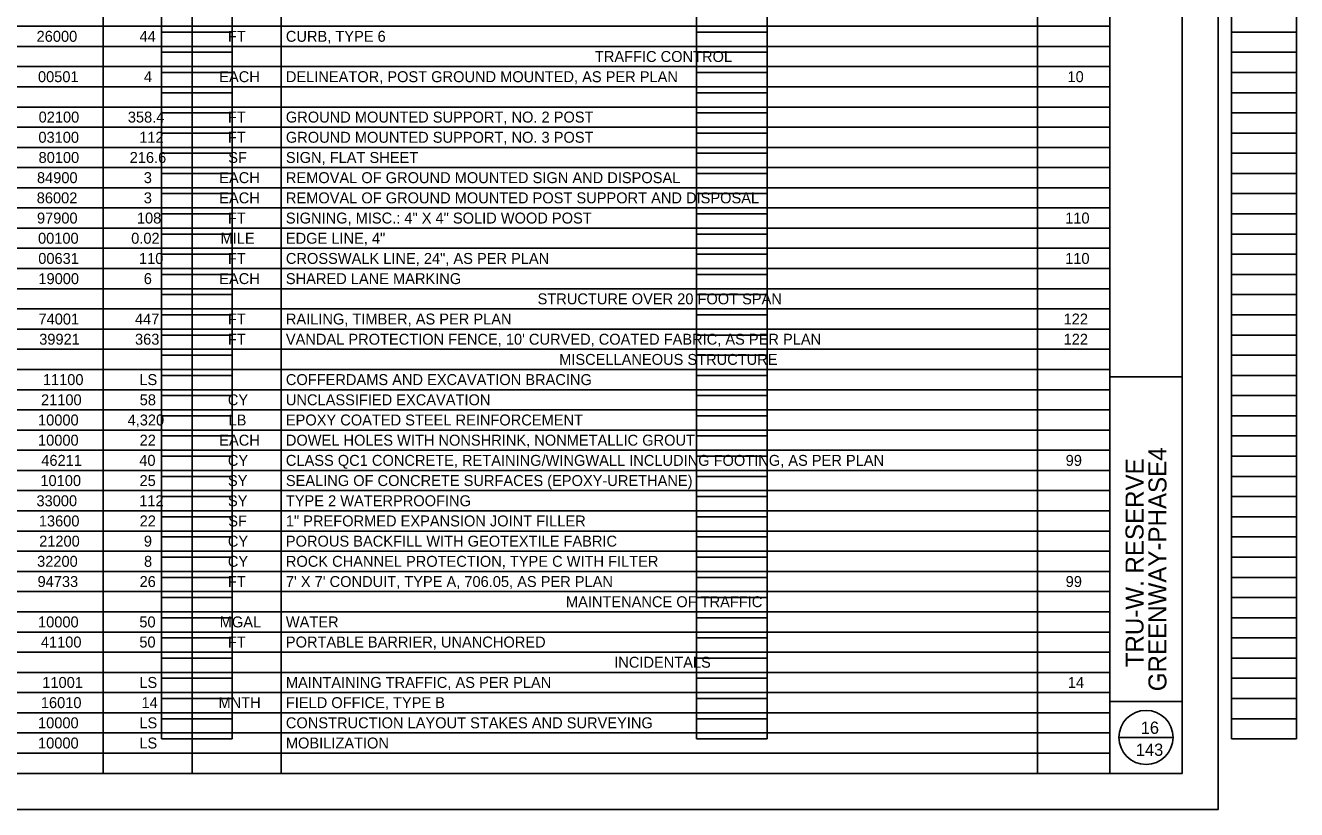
# Model space of a CAD drawing. Extents: x -16 to 102, y -13 to 9.
# Drawn here: x 44.51 to 62.14, y -12.91 to -2.03 of the extents above; entities that cross this region are included whole.
import ezdxf

# ---------------------------------------------------------------- set-up
doc = ezdxf.new("R2010")
doc.units = 0
for name, color, linetype in [('PV_P_EOP', 7, 'Continuous'), ('SH_Border', 7, 'Continuous'), ('SH_Cut_Line', 7, 'Continuous'), ('SH_Data', 7, 'Continuous'), ('TX_P_1', 7, 'Continuous')]:
    doc.layers.add(name, color=color, linetype=linetype)

msp = doc.modelspace()

# ---------------------------------------------------------------- linework, layer by layer
at = {"layer": 'SH_Border'}
for p, q in [((59.554, -12.407), (59.554, 8.593)), ((59.554, -6.907), (60.554, -6.907)), ((59.554, -11.407), (60.554, -11.407))]:
    msp.add_line(p, q, dxfattribs=at)
msp.add_lwpolyline([(29.054, 8.593), (60.554, 8.593), (60.554, -12.407), (29.054, -12.407)], close=True, dxfattribs=at)
at = {"layer": 'SH_Cut_Line'}
msp.add_lwpolyline([(27.054, -12.907), (61.054, -12.907), (61.054, 9.093), (27.054, 9.093)], close=True, dxfattribs=at)
at = {"layer": 'SH_Data'}
for p, q in [((46.402, -11.927), (46.402, 8.233)), ((47.382, -11.927), (47.382, 8.233)), ((53.822, -11.927), (53.822, 8.233)), ((54.802, -11.927), (54.802, 8.233)), ((61.242, -11.927), (61.242, 8.233)), ((62.142, -11.927), (62.142, 8.233)), ((46.402, -2.127), (47.382, -2.127)), ((53.822, -2.127), (54.802, -2.127)), ((61.242, -2.127), (62.142, -2.127)), ((46.402, -2.407), (47.382, -2.407)), ((53.822, -2.407), (54.802, -2.407)), ((61.242, -2.407), (62.142, -2.407)), ((46.402, -2.687), (47.382, -2.687)), ((53.822, -2.687), (54.802, -2.687)), ((61.242, -2.687), (62.142, -2.687)), ((46.402, -2.967), (47.382, -2.967)), ((53.822, -2.967), (54.802, -2.967)), ((61.242, -2.967), (62.142, -2.967)), ((46.402, -3.247), (47.382, -3.247)), ((53.822, -3.247), (54.802, -3.247)), ((61.242, -3.247), (62.142, -3.247)), ((46.402, -3.527), (47.382, -3.527)), ((53.822, -3.527), (54.802, -3.527)), ((61.242, -3.527), (62.142, -3.527)), ((46.402, -3.807), (47.382, -3.807)), ((53.822, -3.807), (54.802, -3.807)), ((61.242, -3.807), (62.142, -3.807)), ((46.402, -4.087), (47.382, -4.087)), ((53.822, -4.087), (54.802, -4.087)), ((61.242, -4.087), (62.142, -4.087)), ((46.402, -4.367), (47.382, -4.367)), ((53.822, -4.367), (54.802, -4.367)), ((61.242, -4.367), (62.142, -4.367)), ((46.402, -4.647), (47.382, -4.647)), ((53.822, -4.647), (54.802, -4.647)), ((61.242, -4.647), (62.142, -4.647)), ((46.402, -4.927), (47.382, -4.927)), ((53.822, -4.927), (54.802, -4.927)), ((61.242, -4.927), (62.142, -4.927)), ((46.402, -5.207), (47.382, -5.207)), ((53.822, -5.207), (54.802, -5.207)), ((61.242, -5.207), (62.142, -5.207)), ((46.402, -5.487), (47.382, -5.487)), ((53.822, -5.487), (54.802, -5.487)), ((61.242, -5.487), (62.142, -5.487)), ((46.402, -5.767), (47.382, -5.767)), ((53.822, -5.767), (54.802, -5.767)), ((61.242, -5.767), (62.142, -5.767)), ((46.402, -6.047), (47.382, -6.047)), ((53.822, -6.047), (54.802, -6.047)), ((61.242, -6.047), (62.142, -6.047)), ((46.402, -6.327), (47.382, -6.327)), ((53.822, -6.327), (54.802, -6.327)), ((61.242, -6.327), (62.142, -6.327)), ((46.402, -6.607), (47.382, -6.607)), ((53.822, -6.607), (54.802, -6.607)), ((61.242, -6.607), (62.142, -6.607)), ((46.402, -6.887), (47.382, -6.887)), ((53.822, -6.887), (54.802, -6.887)), ((61.242, -6.887), (62.142, -6.887)), ((46.402, -7.167), (47.382, -7.167)), ((53.822, -7.167), (54.802, -7.167)), ((61.242, -7.167), (62.142, -7.167)), ((46.402, -7.447), (47.382, -7.447)), ((53.822, -7.447), (54.802, -7.447)), ((61.242, -7.447), (62.142, -7.447)), ((46.402, -7.727), (47.382, -7.727)), ((53.822, -7.727), (54.802, -7.727)), ((61.242, -7.727), (62.142, -7.727)), ((46.402, -8.007), (47.382, -8.007)), ((53.822, -8.007), (54.802, -8.007)), ((61.242, -8.007), (62.142, -8.007)), ((46.402, -8.287), (47.382, -8.287)), ((53.822, -8.287), (54.802, -8.287)), ((61.242, -8.287), (62.142, -8.287)), ((46.402, -8.567), (47.382, -8.567)), ((53.822, -8.567), (54.802, -8.567)), ((61.242, -8.567), (62.142, -8.567)), ((46.402, -8.847), (47.382, -8.847)), ((53.822, -8.847), (54.802, -8.847)), ((61.242, -8.847), (62.142, -8.847)), ((46.402, -9.127), (47.382, -9.127)), ((53.822, -9.127), (54.802, -9.127)), ((61.242, -9.127), (62.142, -9.127)), ((46.402, -9.407), (47.382, -9.407)), ((53.822, -9.407), (54.802, -9.407)), ((61.242, -9.407), (62.142, -9.407)), ((46.402, -9.687), (47.382, -9.687)), ((53.822, -9.687), (54.802, -9.687)), ((61.242, -9.687), (62.142, -9.687)), ((46.402, -9.967), (47.382, -9.967)), ((53.822, -9.967), (54.802, -9.967)), ((61.242, -9.967), (62.142, -9.967)), ((46.402, -10.247), (47.382, -10.247)), ((53.822, -10.247), (54.802, -10.247)), ((61.242, -10.247), (62.142, -10.247)), ((46.402, -10.527), (47.382, -10.527)), ((53.822, -10.527), (54.802, -10.527)), ((61.242, -10.527), (62.142, -10.527)), ((46.402, -10.807), (47.382, -10.807)), ((53.822, -10.807), (54.802, -10.807)), ((61.242, -10.807), (62.142, -10.807)), ((46.402, -11.087), (47.382, -11.087)), ((53.822, -11.087), (54.802, -11.087)), ((61.242, -11.087), (62.142, -11.087)), ((46.402, -11.367), (47.382, -11.367)), ((53.822, -11.367), (54.802, -11.367)), ((61.242, -11.367), (62.142, -11.367)), ((46.402, -11.647), (47.382, -11.647)), ((53.822, -11.647), (54.802, -11.647)), ((61.242, -11.647), (62.142, -11.647)), ((46.402, -11.927), (47.382, -11.927)), ((53.822, -11.927), (54.802, -11.927)), ((59.679, -11.907), (60.429, -11.907)), ((61.242, -11.927), (62.142, -11.927))]:
    msp.add_line(p, q, dxfattribs=at)
msp.add_circle((60.054, -11.907), 0.375, dxfattribs=at)
at = {"layer": 'TX_P_1'}
for p, q in [((45.589, 8.593), (45.589, -12.405)), ((46.824, 8.593), (46.824, -12.405)), ((48.059, 8.593), (48.059, -12.405)), ((58.549, 8.593), (58.549, -12.405)), ((59.554, 8.593), (59.554, -12.405)), ((29.054, -2.046), (59.554, -2.046)), ((29.054, -2.326), (59.554, -2.326)), ((29.054, -2.606), (59.554, -2.606)), ((29.054, -2.886), (59.554, -2.886)), ((29.054, -3.166), (59.554, -3.166)), ((29.054, -3.446), (59.554, -3.446)), ((29.054, -3.726), (59.554, -3.726)), ((29.054, -4.005), (59.554, -4.005)), ((29.054, -4.285), (59.554, -4.285)), ((29.054, -4.565), (59.554, -4.565)), ((29.054, -4.845), (59.554, -4.845)), ((29.054, -5.125), (59.554, -5.125)), ((29.054, -5.405), (59.554, -5.405)), ((29.054, -5.685), (59.554, -5.685)), ((29.054, -5.965), (59.554, -5.965)), ((29.054, -6.245), (59.554, -6.245)), ((29.054, -6.525), (59.554, -6.525)), ((29.054, -6.805), (59.554, -6.805)), ((29.054, -7.085), (59.554, -7.085)), ((29.054, -7.365), (59.554, -7.365)), ((29.054, -7.645), (59.554, -7.645)), ((29.054, -7.925), (59.554, -7.925)), ((29.054, -8.205), (59.554, -8.205)), ((29.054, -8.485), (59.554, -8.485)), ((29.054, -8.765), (59.554, -8.765)), ((29.054, -9.045), (59.554, -9.045)), ((29.054, -9.325), (59.554, -9.325)), ((29.054, -9.605), (59.554, -9.605)), ((29.054, -9.885), (59.554, -9.885)), ((29.054, -10.165), (59.554, -10.165)), ((29.054, -10.445), (59.554, -10.445)), ((29.054, -10.725), (59.554, -10.725)), ((29.054, -11.005), (59.554, -11.005)), ((29.054, -11.285), (59.554, -11.285)), ((29.054, -11.565), (59.554, -11.565)), ((29.054, -11.845), (59.554, -11.845)), ((29.054, -12.125), (59.554, -12.125)), ((29.054, -12.405), (59.554, -12.405))]:
    msp.add_line(p, q, dxfattribs=at)

# ---------------------------------------------------------------- texts
at = {"layer": 'PV_P_EOP'}
for s, p in [('TRAFFIC CONTROL', (52.411, -2.541)), ('STRUCTURE OVER 20 FOOT SPAN ', (51.616, -5.901)), ('MISCELLANEOUS STRUCTURE', (51.915, -6.741)), ('MAINTENANCE OF TRAFFIC', (52.009, -10.101)), ('INCIDENTALS', (52.679, -10.94))]:
    msp.add_text(s, height=0.15151, dxfattribs=at).set_placement(p)
at = {"layer": 'SH_Data'}
for s, p in [('GREENWAY-PHASE4', (60.338, -11.266)), ('TRU-W. RESERVE', (60.02, -10.934))]:
    msp.add_text(s, height=0.25, rotation=90, dxfattribs=at).set_placement(p)
for s, p in [('16', (59.981, -11.857)), ('143', (59.914, -12.162))]:
    msp.add_text(s, height=0.17, dxfattribs=at).set_placement(p)
at = {"layer": 'TX_P_1'}
for s, height, p in [('26000', 0.1515, (44.668, -2.261)), ('44', 0.1515, (46.096, -2.261)), ('FT', 0.1515, (47.322, -2.261)), ('CURB, TYPE 6', 0.15151, (48.125, -2.261)), ('00501', 0.1515, (44.687, -2.821)), ('4', 0.152, (46.156, -2.821)), ('EACH', 0.1515, (47.201, -2.821)), ('DELINEATOR, POST GROUND MOUNTED, AS PER PLAN', 0.15151, (48.125, -2.821)), ('10', 0.1515, (58.965, -2.821)), ('02100', 0.1515, (44.696, -3.381)), ('358.4', 0.1515, (45.933, -3.381)), ('FT', 0.1515, (47.322, -3.381)), ('GROUND MOUNTED SUPPORT, NO. 2 POST', 0.15151, (48.125, -3.381)), ('03100', 0.1515, (44.693, -3.661)), ('112', 0.1515, (46.091, -3.661)), ('FT', 0.1515, (47.322, -3.661)), ('GROUND MOUNTED SUPPORT, NO. 3 POST', 0.15151, (48.125, -3.661)), ('80100', 0.1515, (44.695, -3.941)), ('216.6', 0.1515, (45.959, -3.941)), ('SF', 0.1515, (47.326, -3.941)), ('SIGN, FLAT SHEET', 0.15151, (48.125, -3.941)), ('84900', 0.1515, (44.673, -4.221)), ('3', 0.152, (46.154, -4.221)), ('EACH', 0.1515, (47.201, -4.221)), ('REMOVAL OF GROUND MOUNTED SIGN AND DISPOSAL', 0.15151, (48.125, -4.221)), ('86002', 0.1515, (44.67, -4.501)), ('3', 0.152, (46.154, -4.501)), ('EACH', 0.1515, (47.201, -4.501)), ('REMOVAL OF GROUND MOUNTED POST SUPPORT AND DISPOSAL', 0.15151, (48.125, -4.501)), ('97900', 0.1515, (44.673, -4.781)), ('108', 0.1515, (46.059, -4.781)), ('FT', 0.1515, (47.322, -4.781)), ('SIGNING, MISC.: 4" X 4" SOLID WOOD POST', 0.15151, (48.125, -4.781)), ('110', 0.1515, (58.933, -4.781)), ('00100', 0.1515, (44.688, -5.061)), ('0.02', 0.1515, (45.98, -5.061)), ('MILE', 0.1515, (47.22, -5.061)), ('EDGE LINE, 4"', 0.15151, (48.125, -5.061)), ('00631', 0.1515, (44.691, -5.341)), ('110', 0.1515, (46.088, -5.341)), ('FT', 0.1515, (47.322, -5.341)), ('CROSSWALK LINE, 24", AS PER PLAN', 0.15151, (48.125, -5.341)), ('110', 0.1515, (58.933, -5.341)), ('19000', 0.1515, (44.693, -5.621)), ('6', 0.152, (46.154, -5.621)), ('EACH', 0.1515, (47.201, -5.621)), ('SHARED LANE MARKING', 0.15151, (48.125, -5.621)), ('74001', 0.1515, (44.694, -6.181)), ('447', 0.1515, (46.032, -6.181)), ('FT', 0.1515, (47.322, -6.181)), ('RAILING, TIMBER, AS PER PLAN', 0.15151, (48.125, -6.181)), ('122', 0.1515, (58.911, -6.181)), ('39921', 0.1515, (44.704, -6.461)), ('363', 0.1515, (46.033, -6.461)), ('FT', 0.1515, (47.322, -6.461)), ("VANDAL PROTECTION FENCE, 10' CURVED, COATED FABRIC, AS PER PLAN", 0.15151, (48.125, -6.461)), ('122', 0.1515, (58.911, -6.461)), ('11100', 0.1515, (44.755, -7.021)), ('LS', 0.1515, (46.093, -7.021)), ('COFFERDAMS AND EXCAVATION BRACING', 0.15151, (48.125, -7.021)), ('21100', 0.1515, (44.729, -7.301)), ('58', 0.1515, (46.098, -7.301)), ('CY', 0.1515, (47.32, -7.301)), ('UNCLASSIFIED EXCAVATION', 0.15151, (48.125, -7.301)), ('10000', 0.1515, (44.688, -7.581)), ('4,320', 0.1515, (45.93, -7.581)), ('LB', 0.1515, (47.33, -7.581)), ('EPOXY COATED STEEL REINFORCEMENT', 0.15151, (48.125, -7.581)), ('10000', 0.1515, (44.688, -7.861)), ('22', 0.1515, (46.097, -7.861)), ('EACH', 0.1515, (47.201, -7.861)), ('DOWEL HOLES WITH NONSHRINK, NONMETALLIC GROUT', 0.15151, (48.125, -7.861)), ('46211', 0.1515, (44.733, -8.141)), ('40', 0.1515, (46.092, -8.141)), ('CY', 0.1515, (47.32, -8.141)), ('CLASS QC1 CONCRETE, RETAINING/WINGWALL INCLUDING FOOTING, AS PER PLAN', 0.15151, (48.125, -8.141)), ('99', 0.1515, (58.94, -8.141)), ('10100', 0.1515, (44.721, -8.421)), ('25', 0.1515, (46.096, -8.421)), ('SY', 0.1515, (47.322, -8.421)), ('SEALING OF CONCRETE SURFACES (EPOXY-URETHANE)', 0.15151, (48.125, -8.421)), ('33000', 0.1515, (44.666, -8.701)), ('112', 0.1515, (46.091, -8.701)), ('SY', 0.1515, (47.322, -8.701)), ('TYPE 2 WATERPROOFING', 0.15151, (48.125, -8.701)), ('13600', 0.1515, (44.699, -8.981)), ('22', 0.1515, (46.097, -8.981)), ('SF', 0.1515, (47.326, -8.981)), ('1" PREFORMED EXPANSION JOINT FILLER', 0.15151, (48.125, -8.981)), ('21200', 0.1515, (44.703, -9.261)), ('9', 0.152, (46.155, -9.261)), ('CY', 0.1515, (47.32, -9.261)), ('POROUS BACKFILL WITH GEOTEXTILE FABRIC', 0.15151, (48.125, -9.261)), ('32200', 0.1515, (44.675, -9.541)), ('8', 0.152, (46.157, -9.541)), ('CY', 0.1515, (47.32, -9.541)), ('ROCK CHANNEL PROTECTION, TYPE C WITH FILTER', 0.15151, (48.125, -9.541)), ('94733', 0.1515, (44.681, -9.821)), ('26', 0.1515, (46.096, -9.821)), ('FT', 0.1515, (47.322, -9.821)), ("7' X 7' CONDUIT, TYPE A, 706.05, AS PER PLAN", 0.15151, (48.125, -9.821)), ('99', 0.1515, (58.94, -9.821)), ('10000', 0.1515, (44.688, -10.381)), ('50', 0.1515, (46.093, -10.381)), ('MGAL', 0.1515, (47.208, -10.381)), ('WATER', 0.1515, (48.125, -10.381)), ('41100', 0.1515, (44.727, -10.66)), ('50', 0.1515, (46.093, -10.66)), ('FT', 0.1515, (47.322, -10.66)), ('PORTABLE BARRIER, UNANCHORED', 0.15151, (48.125, -10.66)), ('11001', 0.1515, (44.747, -11.22)), ('LS', 0.1515, (46.093, -11.22)), ('MAINTAINING TRAFFIC, AS PER PLAN', 0.15151, (48.125, -11.22)), ('14', 0.1515, (58.969, -11.22)), ('16010', 0.1515, (44.727, -11.5)), ('14', 0.1515, (46.123, -11.5)), ('MNTH', 0.1515, (47.191, -11.5)), ('FIELD OFFICE, TYPE B', 0.15151, (48.125, -11.5)), ('10000', 0.1515, (44.688, -11.78)), ('LS', 0.1515, (46.093, -11.78)), ('CONSTRUCTION LAYOUT STAKES AND SURVEYING', 0.15151, (48.125, -11.78)), ('10000', 0.1515, (44.688, -12.06)), ('LS', 0.1515, (46.093, -12.06)), ('MOBILIZATION', 0.15151, (48.125, -12.06))]:
    msp.add_text(s, height=height, dxfattribs=at).set_placement(p)

doc.saveas('drawing.dxf')
